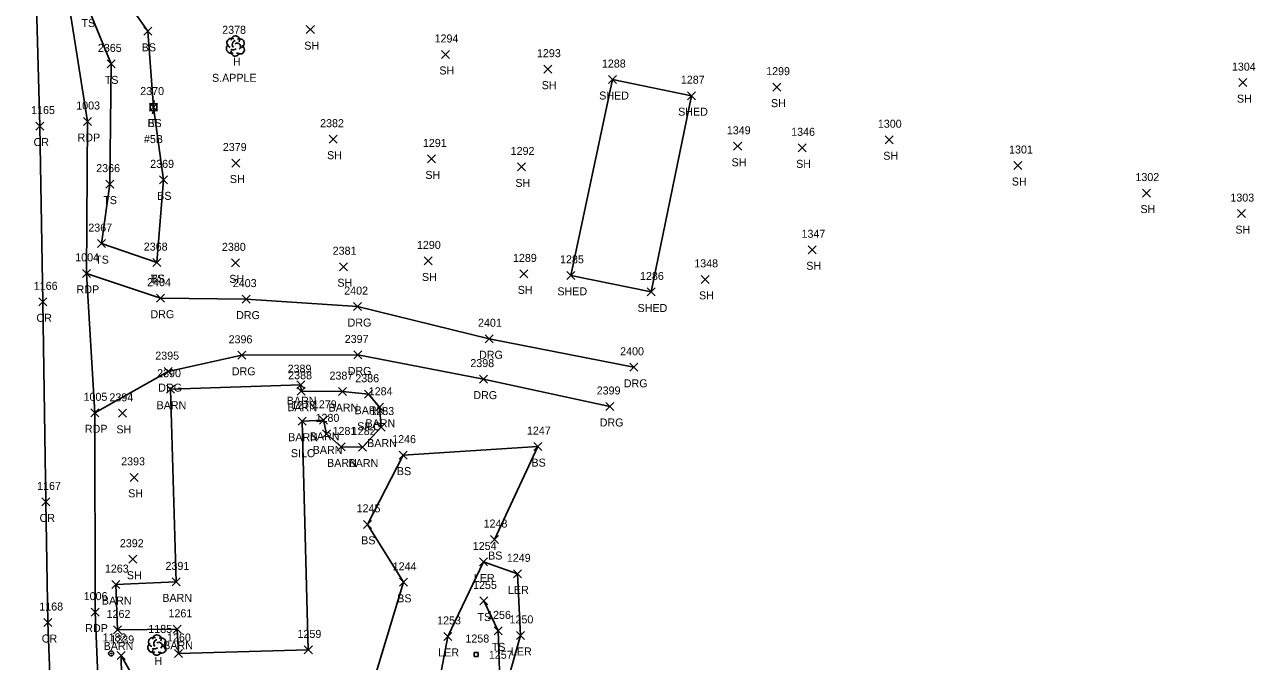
# Model space of a CAD drawing. Extents: x 1609623 to 1616187, y 756677 to 762826.
# Drawn here: x 1610613 to 1610920.4, y 761636.1 to 761795.3 of the extents above; entities that cross this region are included whole.
import ezdxf

# ---------------------------------------------------------------- set-up
doc = ezdxf.new("R2010")
doc.units = 0
for name, color, linetype in [('C_I', 7, 'Continuous'), ('CPBM', 7, 'Continuous'), ('L_A', 7, 'Continuous'), ('L_C', 7, 'Continuous'), ('L_I', 7, 'Continuous'), ('L_TIC', 7, 'Continuous'), ('LARO', 7, 'Continuous'), ('LBC', 7, 'Continuous'), ('LELB', 7, 'Continuous'), ('LTD', 7, 'Continuous'), ('P_A', 7, 'Continuous'), ('P_I', 7, 'Continuous'), ('P_TIC', 7, 'Continuous'), ('PET', 7, 'Continuous'), ('PRC', 7, 'Continuous'), ('R_A', 7, 'Continuous'), ('R_I', 7, 'Continuous'), ('R_TIC', 7, 'Continuous'), ('RDG', 7, 'Continuous'), ('U_A', 7, 'Continuous'), ('U_C', 7, 'Continuous'), ('U_I', 7, 'Continuous'), ('UEPT', 7, 'Continuous'), ('UPGW', 7, 'Continuous')]:
    doc.layers.add(name, color=color, linetype=linetype)

msp = doc.modelspace()

# ---------------------------------------------------------------- linework, layer by layer
at = {"layer": 'CPBM'}
for p, q in [((1610725.29, 761637.35), (1610725.29, 761638.35)), ((1610725.29, 761638.35), (1610726.29, 761638.35)), ((1610726.29, 761637.35), (1610725.29, 761637.35)), ((1610725.79, 761637.85), (1610725.79, 761637.85)), ((1610725.79, 761637.85), (1610725.79, 761637.85)), ((1610726.29, 761638.35), (1610726.29, 761637.35))]:
    msp.add_line(p, q, dxfattribs=at)
at = {"layer": 'L_TIC'}
for points in [[(1610642.79, 761792.62), (1610644.79, 761794.62)], [(1610644.79, 761792.62), (1610642.79, 761794.62)], [(1610683.35, 761793.05), (1610685.35, 761795.05)], [(1610685.35, 761793.05), (1610683.35, 761795.05)], [(1610717.09, 761786.84), (1610719.09, 761788.84)], [(1610719.09, 761786.84), (1610717.09, 761788.84)], [(1610633.58, 761784.48), (1610635.58, 761786.48)], [(1610635.58, 761784.48), (1610633.58, 761786.48)], [(1610742.66, 761783.16), (1610744.66, 761785.16)], [(1610744.66, 761783.16), (1610742.66, 761785.16)], [(1610758.88, 761780.57), (1610760.88, 761782.57)], [(1610760.88, 761780.57), (1610758.88, 761782.57)], [(1610916.35, 761779.79), (1610918.35, 761781.79)], [(1610918.35, 761779.79), (1610916.35, 761781.79)], [(1610778.6, 761776.53), (1610780.6, 761778.53)], [(1610780.6, 761776.53), (1610778.6, 761778.53)], [(1610799.93, 761778.67), (1610801.93, 761780.67)], [(1610801.93, 761778.67), (1610799.93, 761780.67)], [(1610644.2, 761773.69), (1610646.2, 761775.69)], [(1610646.2, 761773.69), (1610644.2, 761775.69)], [(1610689.05, 761765.66), (1610691.05, 761767.66)], [(1610691.05, 761765.66), (1610689.05, 761767.66)], [(1610827.99, 761765.52), (1610829.99, 761767.52)], [(1610829.99, 761765.52), (1610827.99, 761767.52)], [(1610790.11, 761763.89), (1610792.11, 761765.89)], [(1610792.11, 761763.89), (1610790.11, 761765.89)], [(1610806.23, 761763.5), (1610808.23, 761765.5)], [(1610808.23, 761763.5), (1610806.23, 761765.5)], [(1610664.76, 761759.7), (1610666.76, 761761.7)], [(1610666.76, 761759.7), (1610664.76, 761761.7)], [(1610713.6, 761760.73), (1610715.6, 761762.73)], [(1610715.6, 761760.73), (1610713.6, 761762.73)], [(1610736.09, 761758.73), (1610738.09, 761760.73)], [(1610738.09, 761758.73), (1610736.09, 761760.73)], [(1610860.12, 761759.08), (1610862.12, 761761.08)], [(1610862.12, 761759.08), (1610860.12, 761761.08)], [(1610646.66, 761755.5), (1610648.66, 761757.5)], [(1610648.66, 761755.5), (1610646.66, 761757.5)], [(1610633.22, 761754.43), (1610635.22, 761756.43)], [(1610635.22, 761754.43), (1610633.22, 761756.43)], [(1610892.25, 761752.19), (1610894.25, 761754.19)], [(1610894.25, 761752.19), (1610892.25, 761754.19)], [(1610915.97, 761747.06), (1610917.97, 761749.06)], [(1610917.97, 761747.06), (1610915.97, 761749.06)], [(1610631.19, 761739.56), (1610633.19, 761741.56)], [(1610633.19, 761739.56), (1610631.19, 761741.56)], [(1610808.75, 761738.02), (1610810.75, 761740.02)], [(1610810.75, 761738.02), (1610808.75, 761740.02)], [(1610645.04, 761734.81), (1610647.04, 761736.81)], [(1610647.04, 761734.81), (1610645.04, 761736.81)], [(1610645.04, 761734.81), (1610647.04, 761736.81)], [(1610647.04, 761734.81), (1610645.04, 761736.81)], [(1610664.62, 761734.75), (1610666.62, 761736.75)], [(1610666.62, 761734.75), (1610664.62, 761736.75)], [(1610691.62, 761733.78), (1610693.62, 761735.78)], [(1610693.62, 761733.78), (1610691.62, 761735.78)], [(1610712.76, 761735.23), (1610714.76, 761737.23)], [(1610714.76, 761735.23), (1610712.76, 761737.23)], [(1610736.67, 761731.99), (1610738.67, 761733.99)], [(1610738.67, 761731.99), (1610736.67, 761733.99)], [(1610748.43, 761731.63), (1610750.43, 761733.63)], [(1610750.43, 761731.63), (1610748.43, 761733.63)], [(1610781.96, 761730.62), (1610783.96, 761732.62)], [(1610783.96, 761730.62), (1610781.96, 761732.62)], [(1610768.46, 761727.47), (1610770.46, 761729.47)], [(1610770.46, 761727.47), (1610768.46, 761729.47)], [(1610648.43, 761703.17), (1610650.43, 761705.17)], [(1610650.43, 761703.17), (1610648.43, 761705.17)], [(1610680.94, 761704.29), (1610682.94, 761706.29)], [(1610682.94, 761704.29), (1610680.94, 761706.29)], [(1610681.08, 761702.67), (1610683.08, 761704.67)], [(1610683.08, 761702.67), (1610681.08, 761704.67)], [(1610691.4, 761702.57), (1610693.4, 761704.57)], [(1610693.4, 761702.57), (1610691.4, 761704.57)], [(1610697.89, 761701.91), (1610699.89, 761703.91)], [(1610699.89, 761701.91), (1610697.89, 761703.91)], [(1610636.42, 761697.14), (1610638.42, 761699.14)], [(1610638.42, 761697.14), (1610636.42, 761699.14)], [(1610700.62, 761698.66), (1610702.62, 761700.66)], [(1610702.62, 761698.66), (1610700.62, 761700.66)], [(1610681.32, 761695.18), (1610683.32, 761697.18)], [(1610683.32, 761695.18), (1610681.32, 761697.18)], [(1610686.68, 761695.39), (1610688.68, 761697.39)], [(1610688.68, 761695.39), (1610686.68, 761697.39)], [(1610701.03, 761693.71), (1610703.03, 761695.71)], [(1610703.03, 761693.71), (1610701.03, 761695.71)], [(1610687.43, 761692.01), (1610689.43, 761694.01)], [(1610689.43, 761692.01), (1610687.43, 761694.01)], [(1610691.02, 761688.74), (1610693.02, 761690.74)], [(1610693.02, 761688.74), (1610691.02, 761690.74)], [(1610696.4, 761688.71), (1610698.4, 761690.71)], [(1610698.4, 761688.71), (1610696.4, 761690.71)], [(1610740.15, 761688.82), (1610742.15, 761690.82)], [(1610742.15, 761688.82), (1610740.15, 761690.82)], [(1610706.54, 761686.69), (1610708.54, 761688.69)], [(1610708.54, 761686.69), (1610706.54, 761688.69)], [(1610639.35, 761681.14), (1610641.35, 761683.14)], [(1610641.35, 761681.14), (1610639.35, 761683.14)], [(1610697.6, 761669.39), (1610699.6, 761671.39)], [(1610699.6, 761669.39), (1610697.6, 761671.39)], [(1610729.32, 761665.59), (1610731.32, 761667.59)], [(1610731.32, 761665.59), (1610729.32, 761667.59)], [(1610639.03, 761660.67), (1610641.03, 761662.67)], [(1610641.03, 761660.67), (1610639.03, 761662.67)], [(1610726.62, 761659.99), (1610728.62, 761661.99)], [(1610728.62, 761659.99), (1610726.62, 761661.99)], [(1610735.14, 761657.02), (1610737.14, 761659.02)], [(1610737.14, 761657.02), (1610735.14, 761659.02)], [(1610634.76, 761654.33), (1610636.76, 761656.33)], [(1610636.76, 761654.33), (1610634.76, 761656.33)], [(1610649.86, 761655.01), (1610651.86, 761657.01)], [(1610651.86, 761655.01), (1610649.86, 761657.01)], [(1610706.62, 761654.9), (1610708.62, 761656.9)], [(1610708.62, 761654.9), (1610706.62, 761656.9)], [(1610726.7, 761650.24), (1610728.7, 761652.24)], [(1610728.7, 761650.24), (1610726.7, 761652.24)], [(1610635.2, 761643), (1610637.2, 761645)], [(1610637.2, 761643), (1610635.2, 761645)], [(1610650.09, 761643.15), (1610652.09, 761645.15)], [(1610652.09, 761643.15), (1610650.09, 761645.15)], [(1610717.72, 761641.38), (1610719.72, 761643.38)], [(1610719.72, 761641.38), (1610717.72, 761643.38)], [(1610730.26, 761642.76), (1610732.26, 761644.76)], [(1610732.26, 761642.76), (1610730.26, 761644.76)], [(1610735.89, 761641.63), (1610737.89, 761643.63)], [(1610737.89, 761641.63), (1610735.89, 761643.63)], [(1610682.85, 761638.01), (1610684.85, 761640.01)], [(1610684.85, 761638.01), (1610682.85, 761640.01)], [(1610636.08, 761636.62), (1610638.08, 761638.62)], [(1610638.08, 761636.62), (1610636.08, 761638.62)], [(1610650.38, 761637.11), (1610652.38, 761639.11)], [(1610652.38, 761637.11), (1610650.38, 761639.11)]]:
    msp.add_lwpolyline(points, dxfattribs=at)
at = {"layer": 'LARO'}
for points in [[(1610736.14, 761658.02), (1610736.89, 761642.63), (1610732.4, 761626.72), (1610714.63, 761620.87), (1610718.72, 761642.38), (1610727.62, 761660.99)], [(1610727.62, 761660.99), (1610736.14, 761658.02)]]:
    msp.add_lwpolyline(points, dxfattribs=at)
at = {"layer": 'LBC'}
for points in [[(1610749.43, 761732.63), (1610769.46, 761728.47), (1610779.6, 761777.53), (1610759.88, 761781.57)], [(1610759.88, 761781.57), (1610749.43, 761732.63)], [(1610698.89, 761702.91), (1610692.4, 761703.57), (1610682.08, 761703.67), (1610681.94, 761705.29), (1610649.43, 761704.17), (1610650.86, 761656.01)], [(1610698.89, 761702.91), (1610701.62, 761699.66)], [(1610682.32, 761696.18), (1610687.68, 761696.39), (1610688.43, 761693.01), (1610692.02, 761689.74), (1610697.4, 761689.71), (1610702.03, 761694.71), (1610701.62, 761699.66)], [(1610682.32, 761696.18), (1610683.85, 761639.01)], [(1610650.86, 761656.01), (1610635.76, 761655.33)], [(1610683.85, 761639.01), (1610651.38, 761638.11), (1610651.09, 761644.15), (1610636.2, 761644), (1610635.76, 761655.33)]]:
    msp.add_lwpolyline(points, dxfattribs=at)
at = {"layer": 'LELB'}
for points in [[(1610646.04, 761735.81), (1610647.66, 761756.5), (1610645.2, 761774.69), (1610643.79, 761793.62), (1610636.69, 761803.76), (1610641.75, 761824.99), (1610634.48, 761833.22), (1610645.14, 761837.76), (1610647.78, 761833.04)], [(1610628.76, 761799.7), (1610634.58, 761785.48), (1610634.22, 761755.43), (1610632.19, 761740.56), (1610646.04, 761735.81)], [(1610637.62, 761606.21), (1610637.08, 761637.62), (1610642.57, 761627.88), (1610660.87, 761618.63), (1610678.57, 761621), (1610699, 761627.27), (1610707.62, 761655.9), (1610698.6, 761670.39), (1610707.54, 761687.69), (1610741.15, 761689.82), (1610730.32, 761666.59)], [(1610727.7, 761651.24), (1610731.26, 761643.76), (1610731.65, 761633.79)]]:
    msp.add_lwpolyline(points, dxfattribs=at)
at = {"layer": 'LTD'}
for p, q in [((1610665.59, 761790), (1610665.59, 761790)), ((1610665.59, 761790), (1610665.59, 761790)), ((1610645.99, 761640.26), (1610645.99, 761640.26)), ((1610645.99, 761640.26), (1610645.99, 761640.26))]:
    msp.add_line(p, q, dxfattribs=at)
for centre in [(1610665.64, 761791.43), (1610646.04, 761641.69)]:
    msp.add_arc(centre, 1.05, 335.5272, 180.9563, dxfattribs=at)
for centre, major_axis, ratio, start_param, end_param in [((1610664.8, 761790.67), (1.21, -0.51), 0.895232, 1.570796, 4.712389), ((1610665.38, 761790.46), (-0.208, -0.792), 0.645439, 3.141593, 6.283185), ((1610666.09, 761789.83), (-0.5, 0.667), 0.989748, 3.141593, 6.283185), ((1610666.63, 761790.58), (-1.14, -0.48), 0.949671, 1.570796, 4.712389), ((1610664.51, 761789.29), (0.58, -1.04), 0.959034, 3.141593, 6.283185), ((1610665.59, 761788.5), (0.26, 1.06), 0.942809, 1.570796, 4.712389), ((1610665.13, 761789.25), (-0.625, -0.083), 0.423636, 0, 3.141593), ((1610666.59, 761789.17), (-1.09, 0.79), 0.841452, 1.570796, 4.712389), ((1610644.91, 761639.55), (0.58, -1.04), 0.959034, 3.141593, 6.283185), ((1610645.2, 761640.92), (1.21, -0.51), 0.895232, 1.570796, 4.712389), ((1610645.78, 761640.71), (-0.208, -0.792), 0.645439, 3.141593, 6.283185), ((1610646.49, 761640.09), (-0.5, 0.667), 0.989748, 3.141593, 6.283185), ((1610646.99, 761639.42), (-1.09, 0.79), 0.841452, 1.570796, 4.712389), ((1610647.03, 761640.84), (-1.14, -0.48), 0.949671, 1.570796, 4.712389), ((1610645.99, 761638.76), (0.26, 1.06), 0.942809, 1.570796, 4.712389), ((1610645.53, 761639.51), (-0.625, -0.083), 0.423636, 0, 3.141593)]:
    msp.add_ellipse(centre, major_axis=major_axis, ratio=ratio, start_param=start_param, end_param=end_param, dxfattribs=at)
at = {"layer": 'P_TIC'}
for points in [[(1610627.71, 761770.08), (1610629.71, 761772.08)], [(1610629.71, 761770.08), (1610627.71, 761772.08)], [(1610615.76, 761768.94), (1610617.76, 761770.94)], [(1610617.76, 761768.94), (1610615.76, 761770.94)], [(1610627.46, 761732.13), (1610629.46, 761734.13)], [(1610629.46, 761732.13), (1610627.46, 761734.13)], [(1610616.49, 761725.01), (1610618.49, 761727.01)], [(1610618.49, 761725.01), (1610616.49, 761727.01)], [(1610629.54, 761697.27), (1610631.54, 761699.27)], [(1610631.54, 761697.27), (1610629.54, 761699.27)], [(1610617.27, 761674.99), (1610619.27, 761676.99)], [(1610619.27, 761674.99), (1610617.27, 761676.99)], [(1610629.63, 761647.45), (1610631.63, 761649.45)], [(1610631.63, 761647.45), (1610629.63, 761649.45)], [(1610617.81, 761644.85), (1610619.81, 761646.85)], [(1610619.81, 761644.85), (1610617.81, 761646.85)]]:
    msp.add_lwpolyline(points, dxfattribs=at)
at = {"layer": 'PET'}
msp.add_lwpolyline([(1610609.92, 761821.12), (1610621.19, 761822.12), (1610623.98, 761800.55), (1610628.71, 761771.08), (1610628.46, 761733.13), (1610630.54, 761698.27), (1610630.63, 761648.45), (1610632.48, 761602.64)], dxfattribs=at)
at = {"layer": 'PRC'}
msp.add_lwpolyline([(1610615.34, 761821.26), (1610616.76, 761769.94), (1610617.49, 761726.01), (1610618.27, 761675.99), (1610618.81, 761645.85), (1610620.71, 761596.25), (1610622.2, 761543.73), (1610623.77, 761494.01), (1610624.8, 761445.35), (1610626.12, 761399.37), (1610627.46, 761348.43), (1610629.43, 761292.43), (1610633.7, 761219.48)], dxfattribs=at)
at = {"layer": 'R_TIC'}
for points in [[(1610645.92, 761725.92), (1610647.92, 761727.92)], [(1610647.92, 761725.92), (1610645.92, 761727.92)], [(1610667.32, 761725.69), (1610669.32, 761727.69)], [(1610669.32, 761725.69), (1610667.32, 761727.69)], [(1610695.16, 761723.82), (1610697.16, 761725.82)], [(1610697.16, 761723.82), (1610695.16, 761725.82)], [(1610728.01, 761715.78), (1610730.01, 761717.78)], [(1610730.01, 761715.78), (1610728.01, 761717.78)], [(1610666.25, 761711.64), (1610668.25, 761713.64)], [(1610668.25, 761711.64), (1610666.25, 761713.64)], [(1610695.2, 761711.73), (1610697.2, 761713.73)], [(1610697.2, 761711.73), (1610695.2, 761713.73)], [(1610764.17, 761708.64), (1610766.17, 761710.64)], [(1610766.17, 761708.64), (1610764.17, 761710.64)], [(1610647.87, 761707.56), (1610649.87, 761709.56)], [(1610649.87, 761707.56), (1610647.87, 761709.56)], [(1610726.58, 761705.69), (1610728.58, 761707.69)], [(1610728.58, 761705.69), (1610726.58, 761707.69)], [(1610758.16, 761698.85), (1610760.16, 761700.85)], [(1610760.16, 761698.85), (1610758.16, 761700.85)]]:
    msp.add_lwpolyline(points, dxfattribs=at)
at = {"layer": 'RDG'}
for points in [[(1610646.92, 761726.92), (1610628.46, 761733.13)], [(1610765.17, 761709.64), (1610729.01, 761716.78), (1610696.16, 761724.82), (1610668.32, 761726.69), (1610646.92, 761726.92)], [(1610648.87, 761708.56), (1610667.25, 761712.64), (1610696.2, 761712.73), (1610727.58, 761706.69), (1610759.16, 761699.85)], [(1610648.87, 761708.56), (1610630.54, 761698.27)]]:
    msp.add_lwpolyline(points, dxfattribs=at)
at = {"layer": 'UEPT'}
for p, q in [((1610644.37, 761773.85), (1610644.37, 761775.52)), ((1610644.37, 761775.52), (1610646.03, 761775.52)), ((1610645.37, 761776.35), (1610645.2, 761775.52)), ((1610646.03, 761775.52), (1610646.03, 761773.85)), ((1610646.03, 761773.85), (1610644.37, 761773.85)), ((1610644.95, 761773.02), (1610645.2, 761773.85)), ((1610645.2, 761774.69), (1610645.2, 761774.69))]:
    msp.add_line(p, q, dxfattribs=at)
at = {"layer": 'UPGW'}
for radius in [0.625, 0.0833]:
    msp.add_circle((1610634.58, 761638.12), radius, dxfattribs=at)

# ---------------------------------------------------------------- texts
at = {"layer": 'C_I'}
msp.add_text('1258', height=2, dxfattribs=at).set_placement((1610723.1, 761640.85))
at = {"layer": 'L_A'}
for s, p in [('TS', (1610627.17, 761794.7)), ('BS', (1610642.23, 761788.62)), ('SH', (1610682.84, 761789.05)), ('H', (1610665.02, 761785)), ('SH', (1610716.58, 761782.84)), ('TS', (1610632.99, 761780.48)), ('SH', (1610742.15, 761779.16)), ('SHED', (1610756.52, 761776.57)), ('SH', (1610799.42, 761774.67)), ('SH', (1610915.84, 761775.79)), ('SHED', (1610776.24, 761772.53)), ('BS', (1610643.64, 761769.69)), ('SH', (1610688.53, 761761.66)), ('SH', (1610827.48, 761761.52)), ('SH', (1610789.59, 761759.89)), ('SH', (1610805.72, 761759.5)), ('SH', (1610664.25, 761755.7)), ('SH', (1610713.09, 761756.73)), ('SH', (1610735.58, 761754.73)), ('SH', (1610859.6, 761755.08)), ('TS', (1610632.63, 761750.43)), ('BS', (1610646.1, 761751.5)), ('SH', (1610891.74, 761748.19)), ('SH', (1610915.46, 761743.06)), ('TS', (1610630.59, 761735.56)), ('SH', (1610808.24, 761734.02)), ('TS', (1610644.45, 761730.81)), ('BS', (1610644.48, 761730.81)), ('SH', (1610664.11, 761730.75)), ('SH', (1610712.24, 761731.23)), ('SH', (1610691.11, 761729.78)), ('SH', (1610736.16, 761727.99)), ('SHED', (1610746.07, 761727.63)), ('SH', (1610781.45, 761726.62)), ('SHED', (1610766.1, 761723.47)), ('BARN', (1610678.45, 761700.29)), ('BARN', (1610645.94, 761699.17)), ('BARN', (1610678.6, 761698.67)), ('BARN', (1610688.91, 761698.57)), ('BARN', (1610695.41, 761697.91)), ('BARN', (1610698.13, 761694.66)), ('SH', (1610635.9, 761693.14)), ('BARN', (1610678.83, 761691.18)), ('BARN', (1610684.2, 761691.39)), ('BARN', (1610684.94, 761688.01)), ('BARN', (1610698.54, 761689.71)), ('BARN', (1610688.53, 761684.74)), ('BARN', (1610693.91, 761684.71)), ('BS', (1610739.59, 761684.82)), ('BS', (1610705.98, 761682.69)), ('SH', (1610638.84, 761677.14)), ('BS', (1610697.05, 761665.39)), ('BS', (1610728.76, 761661.59)), ('SH', (1610638.51, 761656.67)), ('LER', (1610725.2, 761655.99)), ('BARN', (1610632.28, 761650.33)), ('BARN', (1610647.37, 761651.01)), ('BS', (1610706.06, 761650.9)), ('LER', (1610733.72, 761653.02)), ('TS', (1610726.11, 761646.24)), ('BARN', (1610632.71, 761639)), ('BARN', (1610647.6, 761639.15)), ('TS', (1610729.67, 761638.76)), ('H', (1610645.42, 761635.26)), ('LER', (1610716.3, 761637.38)), ('LER', (1610734.47, 761637.63))]:
    msp.add_text(s, height=2, dxfattribs=at).set_placement(p)
at = {"layer": 'L_C'}
for s, p in [('S.APPLE', (1610659.78, 761781)), ('SILO', (1610696.07, 761693.91)), ('SILO', (1610679.49, 761687.18))]:
    msp.add_text(s, height=2, dxfattribs=at).set_placement(p)
at = {"layer": 'L_I'}
for s, p in [('2378', (1610662.33, 761793)), ('2365', (1610631.27, 761788.48)), ('1294', (1610715.39, 761790.84)), ('1293', (1610740.97, 761787.16)), ('1288', (1610757.19, 761784.57)), ('1299', (1610798.23, 761782.67)), ('1304', (1610914.58, 761783.79)), ('1287', (1610776.91, 761780.53)), ('2370', (1610641.85, 761777.69)), ('2382', (1610686.79, 761769.66)), ('1349', (1610788.4, 761767.89)), ('1346', (1610804.48, 761767.5)), ('1300', (1610826.13, 761769.52)), ('1291', (1610712.47, 761764.73)), ('2379', (1610662.49, 761763.7)), ('1292', (1610734.4, 761762.73)), ('1301', (1610858.91, 761763.08)), ('2366', (1610630.86, 761758.43)), ('2369', (1610644.35, 761759.5)), ('1302', (1610890.48, 761756.19)), ('1303', (1610914.2, 761751.06)), ('2367', (1610628.88, 761743.56)), ('1347', (1610807.06, 761742.02)), ('2368', (1610642.74, 761738.81)), ('2368', (1610642.74, 761738.81)), ('2380', (1610662.27, 761738.75)), ('2381', (1610689.93, 761737.78)), ('1290', (1610710.98, 761739.23)), ('1289', (1610734.97, 761735.99)), ('1285', (1610746.73, 761735.63)), ('1348', (1610780.27, 761734.62)), ('1286', (1610766.71, 761731.47)), ('2390', (1610646.08, 761707.17)), ('2389', (1610678.67, 761708.29)), ('2388', (1610678.82, 761706.67)), ('2387', (1610689.14, 761706.57)), ('2386', (1610695.58, 761705.91)), ('1284', (1610698.93, 761702.66)), ('2394', (1610634.16, 761701.14)), ('1279', (1610684.98, 761699.39)), ('1278', (1610679.63, 761699.18)), ('1283', (1610699.34, 761697.71)), ('1280', (1610685.65, 761696.01)), ('1281', (1610689.9, 761692.74)), ('1282', (1610694.71, 761692.71)), ('1246', (1610704.79, 761690.69)), ('1247', (1610738.46, 761692.82)), ('2393', (1610637.09, 761685.14)), ('1245', (1610695.91, 761673.39)), ('1248', (1610727.63, 761669.59)), ('2392', (1610636.77, 761664.67)), ('1254', (1610724.93, 761663.99)), ('1249', (1610733.44, 761661.02)), ('1263', (1610633.02, 761658.33)), ('2391', (1610648.17, 761659.01)), ('1244', (1610704.92, 761658.9)), ('1255', (1610725, 761654.24)), ('1261', (1610648.92, 761647.15)), ('1262', (1610633.46, 761647)), ('1253', (1610716.03, 761645.38)), ('1256', (1610728.51, 761646.76)), ('1250', (1610734.11, 761645.63)), ('1185', (1610643.87, 761643.26)), ('1260', (1610648.55, 761641.11)), ('1259', (1610681.15, 761642.01)), ('1239', (1610634.38, 761640.62)), ('1257', (1610728.95, 761636.79))]:
    msp.add_text(s, height=2, dxfattribs=at).set_placement(p)
at = {"layer": 'P_A'}
for s, p in [('CR', (1610615.2, 761764.94)), ('RDP', (1610626.2, 761766.08)), ('RDP', (1610625.95, 761728.13)), ('CR', (1610615.92, 761721.01)), ('RDP', (1610628.03, 761693.27)), ('CR', (1610616.7, 761670.99)), ('RDP', (1610628.12, 761643.45)), ('CR', (1610617.24, 761640.85))]:
    msp.add_text(s, height=2, dxfattribs=at).set_placement(p)
at = {"layer": 'P_I'}
for s, p in [('1003', (1610625.86, 761774.08)), ('1165', (1610614.59, 761772.94)), ('1004', (1610625.61, 761736.13)), ('1166', (1610615.26, 761729.01)), ('1005', (1610627.69, 761701.27)), ('1167', (1610616.09, 761678.99)), ('1006', (1610627.73, 761651.45)), ('1168', (1610616.64, 761648.85))]:
    msp.add_text(s, height=2, dxfattribs=at).set_placement(p)
at = {"layer": 'R_A'}
for p in [(1610644.41, 761721.92), (1610665.81, 761721.69), (1610693.65, 761719.82), (1610726.5, 761711.78), (1610664.73, 761707.64), (1610693.69, 761707.73), (1610646.36, 761703.56), (1610762.66, 761704.64), (1610725.07, 761701.69), (1610756.65, 761694.85)]:
    msp.add_text('DRG', height=2, dxfattribs=at).set_placement(p)
at = {"layer": 'R_I'}
for s, p in [('2404', (1610643.58, 761729.92)), ('2403', (1610664.98, 761729.69)), ('2402', (1610692.82, 761727.82)), ('2401', (1610726.24, 761719.78)), ('2396', (1610663.93, 761715.64)), ('2397', (1610692.94, 761715.73)), ('2400', (1610761.75, 761712.64)), ('2395', (1610645.61, 761711.56)), ('2398', (1610724.32, 761709.69)), ('2399', (1610755.89, 761702.85))]:
    msp.add_text(s, height=2, dxfattribs=at).set_placement(p)
at = {"layer": 'U_A'}
msp.add_text('EL', height=2, dxfattribs=at).set_placement((1610643.73, 761769.69))
at = {"layer": 'U_C'}
msp.add_text('#5B', height=2, dxfattribs=at).set_placement((1610642.78, 761765.69))
at = {"layer": 'U_I'}
for s, p in [('2370', (1610641.85, 761777.69)), ('1182', (1610632.46, 761641.12))]:
    msp.add_text(s, height=2, dxfattribs=at).set_placement(p)

doc.saveas('drawing.dxf')
